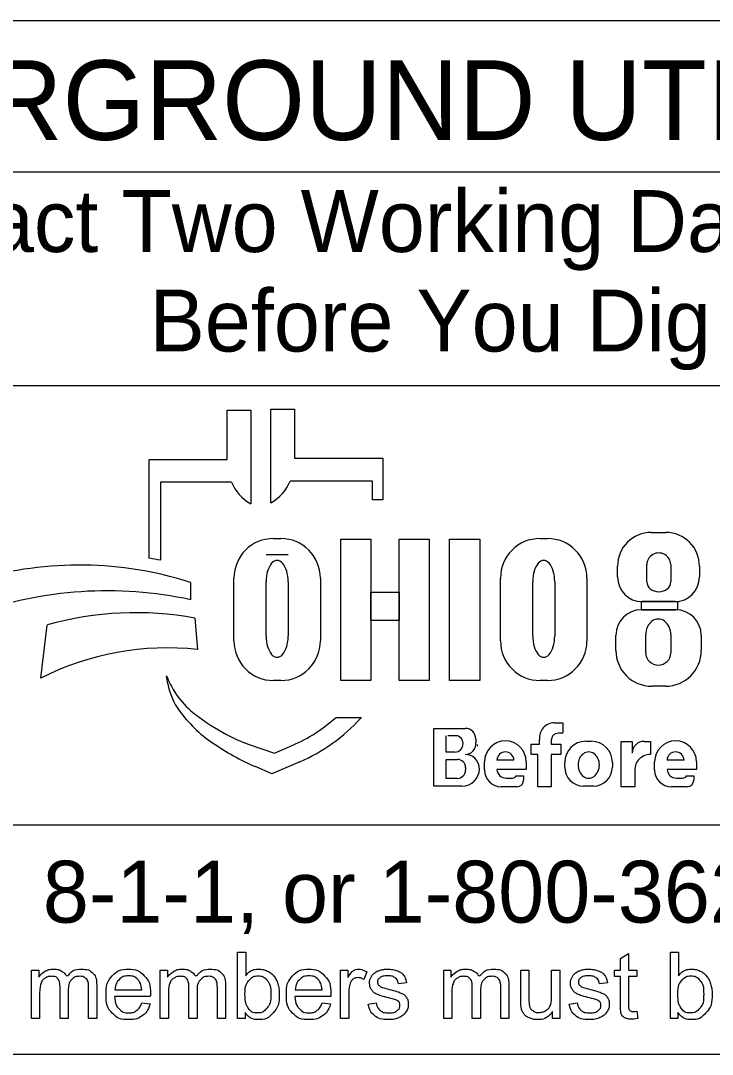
# Model space of a CAD drawing. Extents: x 0 to 59.1, y -2.4 to 22.
# Drawn here: x 4.266 to 5.83, y 2.633 to 4.97 of the extents above; entities that cross this region are included whole.
import ezdxf

# ---------------------------------------------------------------- set-up
doc = ezdxf.new("R2010")
doc.units = 0
doc.layers.add('SH_Data', color=7, linetype='Continuous')
doc.layers.add('SH_Text', color=7, linetype='Continuous')

msp = doc.modelspace()

# ---------------------------------------------------------------- linework, layer by layer
at = {"layer": 'SH_Data'}
for p, q in [((7.6263, 4.9702), (3.3763, 4.9702)), ((3.3763, 4.6287), (7.6263, 4.6287)), ((3.3763, 4.1453), (7.6263, 4.1453)), ((7.6263, 3.1506), (3.3763, 3.1506)), ((7.6263, 2.6327), (3.3763, 2.6327))]:
    msp.add_line(p, q, dxfattribs=at)
at = {"layer": 'SH_Text'}
for p, q in [((4.8317, 3.88), (4.8317, 4.092)), ((4.8317, 4.092), (4.8853, 4.092)), ((4.8853, 4.092), (4.8853, 3.9806)), ((4.7324, 3.9782), (4.7324, 4.0897)), ((4.7324, 4.0897), (4.786, 4.0897)), ((4.786, 4.0897), (4.786, 3.8777)), ((4.5564, 3.7543), (4.5564, 3.9782)), ((4.5564, 3.9782), (4.7324, 3.9782)), ((4.8853, 3.9806), (5.0846, 3.9806)), ((5.0846, 3.9806), (5.0846, 3.8867)), ((5.0613, 3.9291), (4.8749, 3.9291)), ((5.0613, 3.8867), (5.0613, 3.9291)), ((4.5817, 3.9268), (4.5817, 3.7499)), ((4.7428, 3.9268), (4.5817, 3.9268)), ((5.0846, 3.8867), (5.0613, 3.8867)), ((5.6919, 3.813), (5.7247, 3.813)), ((4.8374, 3.799), (4.8539, 3.799)), ((5.4404, 3.799), (5.4569, 3.799)), ((4.8706, 3.762), (4.8208, 3.762)), ((5.6818, 3.7011), (5.6818, 3.7403)), ((5.7359, 3.7403), (5.7359, 3.7011)), ((5.6156, 3.7124), (5.6156, 3.7367)), ((5.801, 3.7367), (5.801, 3.7124)), ((4.6497, 3.6997), (4.6497, 3.6608)), ((4.7479, 3.5676), (4.7479, 3.7096)), ((4.8208, 3.579), (4.8208, 3.7013)), ((4.8706, 3.7013), (4.8706, 3.579)), ((4.9434, 3.7096), (4.9434, 3.5676)), ((5.3509, 3.5676), (5.3509, 3.7096)), ((5.4238, 3.579), (5.4238, 3.7013)), ((5.4736, 3.7013), (5.4736, 3.579)), ((5.5464, 3.7096), (5.5464, 3.5676)), ((5.745, 3.6564), (5.6716, 3.6564)), ((5.6698, 3.6381), (5.7471, 3.6381)), ((4.3109, 3.4835), (4.3256, 3.6036)), ((4.6597, 3.6191), (4.6659, 3.5481)), ((5.6119, 3.5462), (5.6119, 3.5802)), ((5.6794, 3.5403), (5.6794, 3.5812)), ((5.7363, 3.5812), (5.7363, 3.5403)), ((5.805, 3.5802), (5.805, 3.5462)), ((4.5986, 3.4706), (4.5955, 3.4885)), ((4.8539, 3.4781), (4.8374, 3.4781)), ((5.4569, 3.4781), (5.4404, 3.4781)), ((5.7241, 3.4653), (5.6929, 3.4653)), ((4.9789, 3.3947), (5.0363, 3.3947)), ((5.2002, 3.239), (5.2002, 3.3697)), ((5.2002, 3.3697), (5.2713, 3.3697)), ((5.4727, 3.3825), (5.4922, 3.3825)), ((5.4922, 3.3825), (5.4922, 3.3595)), ((5.2281, 3.3162), (5.2281, 3.3532)), ((5.2533, 3.3532), (5.2321, 3.3532)), ((5.2951, 3.3459), (5.2951, 3.338)), ((5.4395, 3.3341), (5.4395, 3.3446)), ((5.4922, 3.359), (5.482, 3.359)), ((4.7804, 3.3344), (4.8399, 3.3139)), ((4.8399, 3.3139), (4.8809, 3.3317)), ((5.4201, 3.3111), (5.4201, 3.3341)), ((5.4201, 3.3341), (5.4395, 3.3341)), ((5.4656, 3.3425), (5.4656, 3.3341)), ((5.4656, 3.3341), (5.4871, 3.3341)), ((5.4871, 3.3341), (5.4871, 3.3111)), ((5.544, 3.3407), (5.5561, 3.3407)), ((5.6242, 3.2378), (5.6242, 3.3405)), ((5.6242, 3.3405), (5.6488, 3.3405)), ((5.6488, 3.3405), (5.6488, 3.3136)), ((5.676, 3.3405), (5.6899, 3.3405)), ((5.6899, 3.3405), (5.6899, 3.3108)), ((5.2475, 3.3162), (5.2281, 3.3162)), ((5.2281, 3.2568), (5.2281, 3.2997)), ((5.2281, 3.2997), (5.2537, 3.2997)), ((5.3813, 3.2981), (5.3428, 3.2981)), ((5.435, 3.3111), (5.4201, 3.3111)), ((5.435, 3.2378), (5.435, 3.3111)), ((5.4871, 3.3111), (5.4656, 3.3111)), ((5.4656, 3.3111), (5.4656, 3.2378)), ((5.7662, 3.2981), (5.7277, 3.2981)), ((4.8338, 3.2668), (4.7965, 3.2833)), ((4.8971, 3.2943), (4.8338, 3.2668)), ((5.2718, 3.2816), (5.2718, 3.2752)), ((5.3031, 3.2786), (5.3031, 3.2783)), ((5.3147, 3.2758), (5.3147, 3.2942)), ((5.4092, 3.2765), (5.3428, 3.2765)), ((5.4092, 3.2942), (5.4092, 3.2765)), ((5.4961, 3.2821), (5.4961, 3.2929)), ((5.6039, 3.2929), (5.6039, 3.2821)), ((5.6547, 3.2759), (5.6547, 3.2378)), ((5.6996, 3.2758), (5.6996, 3.2942)), ((5.7941, 3.2765), (5.7277, 3.2765)), ((5.7941, 3.2942), (5.7941, 3.2765)), ((5.2534, 3.2568), (5.2281, 3.2568)), ((5.3637, 3.2573), (5.3779, 3.2573)), ((5.3864, 3.2628), (5.4033, 3.2628)), ((5.4033, 3.2628), (5.4033, 3.253)), ((5.7487, 3.2573), (5.7628, 3.2573)), ((5.7713, 3.2628), (5.7882, 3.2628)), ((5.7882, 3.2628), (5.7882, 3.253)), ((5.2638, 3.239), (5.2002, 3.239)), ((5.3881, 3.2378), (5.3527, 3.2378)), ((5.4656, 3.2378), (5.435, 3.2378)), ((5.5611, 3.2393), (5.5389, 3.2393)), ((5.6547, 3.2378), (5.6242, 3.2378)), ((5.773, 3.2378), (5.7376, 3.2378))]:
    msp.add_line(p, q, dxfattribs=at)
for points in [[(4.9898, 3.798), (5.0578, 3.798), (5.0578, 3.478), (4.9898, 3.478)], [(5.1219, 3.798), (5.1899, 3.798), (5.1899, 3.478), (5.1219, 3.478)], [(5.2353, 3.798), (5.304, 3.798), (5.304, 3.478), (5.2353, 3.478)], [(5.0578, 3.6781), (5.1219, 3.6781), (5.1219, 3.6141), (5.0578, 3.6141)], [(5.6695, 3.6565), (5.7512, 3.6565), (5.7512, 3.638), (5.6695, 3.638)]]:
    msp.add_lwpolyline(points, close=True, dxfattribs=at)
for points in [[(4.7732, 2.7139), (4.7561, 2.7139), (4.7561, 2.864), (4.7745, 2.864), (4.7745, 2.8105)], [(5.6221, 2.7457), (5.6221, 2.8084), (5.6085, 2.8084), (5.6085, 2.8227), (5.6221, 2.8227), (5.6221, 2.8496), (5.6405, 2.8607), (5.6405, 2.8227), (5.659, 2.8227), (5.659, 2.8084), (5.6405, 2.8084), (5.6405, 2.7446)], [(5.7522, 2.7139), (5.7352, 2.7139), (5.7352, 2.864), (5.7536, 2.864), (5.7536, 2.8105)], [(4.2901, 2.7139), (4.2901, 2.8227), (4.3066, 2.8227), (4.3066, 2.8073)], [(4.5814, 2.7139), (4.5814, 2.8227), (4.5979, 2.8227), (4.5979, 2.8073)], [(4.9892, 2.7139), (4.9892, 2.8227), (5.0058, 2.8227), (5.0058, 2.8062)], [(5.0483, 2.8192), (5.0418, 2.8021)], [(5.2224, 2.7139), (5.2224, 2.8227), (5.2389, 2.8227), (5.2389, 2.8073)], [(5.3968, 2.7553), (5.3968, 2.8227), (5.4152, 2.8227), (5.4152, 2.7624)], [(5.4665, 2.7644), (5.4665, 2.8227), (5.4849, 2.8227), (5.4849, 2.7139), (5.4684, 2.7139)], [(4.3732, 2.777), (4.3732, 2.7139), (4.3547, 2.7139), (4.3547, 2.7845)], [(4.4376, 2.7885), (4.4376, 2.7139), (4.4192, 2.7139), (4.4192, 2.7824)], [(4.6645, 2.777), (4.6645, 2.7139), (4.6461, 2.7139), (4.6461, 2.7845)], [(4.729, 2.7885), (4.729, 2.7139), (4.7105, 2.7139), (4.7105, 2.7824)], [(5.1382, 2.7945), (5.1202, 2.7921)], [(5.3055, 2.777), (5.3055, 2.7139), (5.2871, 2.7139), (5.2871, 2.7845)], [(5.37, 2.7885), (5.37, 2.7139), (5.3515, 2.7139), (5.3515, 2.7824)], [(5.5928, 2.7945), (5.5747, 2.7921)], [(4.3085, 2.7703), (4.3085, 2.7139), (4.2901, 2.7139)], [(4.5588, 2.7635), (4.4777, 2.7635)], [(4.4787, 2.7786), (4.5395, 2.7786)], [(4.5999, 2.7703), (4.5999, 2.7139), (4.5814, 2.7139)], [(4.9668, 2.7635), (4.8857, 2.7635)], [(4.8867, 2.7786), (4.9475, 2.7786)], [(5.0077, 2.7708), (5.0077, 2.7139), (4.9892, 2.7139)], [(5.2409, 2.7703), (5.2409, 2.7139), (5.2224, 2.7139)], [(4.5393, 2.749), (4.5583, 2.7466)], [(4.9473, 2.749), (4.9663, 2.7466)], [(5.0518, 2.7464), (5.07, 2.7492)], [(5.5064, 2.7464), (5.5246, 2.7492)], [(4.7732, 2.7275), (4.7732, 2.7139)], [(5.4684, 2.7139), (5.4684, 2.7299)], [(5.659, 2.7303), (5.6616, 2.714)], [(5.7522, 2.7275), (5.7522, 2.7139)]]:
    msp.add_lwpolyline(points, dxfattribs=at)
for centre, radius, start, end in [((4.7836, 3.9659), 0.0985, 299.2531, 338.0704), ((4.8341, 3.9636), 0.0985, 201.9296, 240.7469), ((5.6919, 3.7367), 0.0763, 90, 180), ((5.7247, 3.7367), 0.0763, 0, 90), ((4.8374, 3.7096), 0.0895, 90, 180), ((4.8539, 3.7096), 0.0895, 0, 90), ((5.4404, 3.7096), 0.0895, 90, 180), ((5.4569, 3.7096), 0.0895, 0, 90), ((4.4283, 2.9454), 0.8191, 79.2074, 81.0007), ((4.3985, 2.9201), 0.8191, 72.1402, 106.3144), ((5.6716, 3.7124), 0.056, 180, 270), ((5.745, 3.7124), 0.056, 270, 0), ((4.4616, 2.789), 0.8919, 77.8238, 109.8274), ((4.5255, 2.8993), 0.7322, 79.44, 105.8467), ((5.6698, 3.5802), 0.0579, 90, 180), ((5.7471, 3.5802), 0.0579, 0, 90), ((4.8374, 3.5676), 0.0895, 180, 270), ((4.8539, 3.5676), 0.0895, 270, 0), ((5.4404, 3.5676), 0.0895, 180, 270), ((5.4569, 3.5676), 0.0895, 270, 0), ((4.5975, 2.9161), 0.6357, 83.8248, 116.8021), ((5.6929, 3.5462), 0.081, 180, 270), ((5.7241, 3.5462), 0.081, 270, 0), ((4.7829, 3.5606), 0.2008, 201.0457, 232.5314), ((4.7399, 3.4947), 0.1433, 189.6817, 216.0884), ((4.8735, 3.5921), 0.3088, 216.0884, 235.7167), ((4.9754, 3.8119), 0.5173, 232.5314, 241.794), ((4.7375, 3.6621), 0.3602, 293.4582, 312.0712), ((4.7375, 3.6621), 0.401, 293.4582, 317.8286), ((5.2713, 3.3459), 0.0238, 0, 90), ((5.4727, 3.349), 0.0335, 90, 187.5187), ((4.8903, 3.653), 0.3371, 241.794, 250.9821), ((5.2494, 3.3363), 0.0169, 357.8325, 90), ((5.482, 3.3425), 0.0165, 90, 180), ((5.0401, 3.8364), 0.6044, 235.7167, 246.2325), ((5.2475, 3.335), 0.0187, 270, 2.0582), ((5.2709, 3.3352), 0.0243, 270, 6.6529), ((5.2815, 3.3337), 0.0175, 347.4023, 0), ((5.362, 3.2942), 0.0473, 0, 180), ((5.544, 3.2929), 0.0478, 90, 180), ((5.5561, 3.2929), 0.0478, 0, 90), ((5.6756, 3.3136), 0.0269, 89.2449, 180), ((5.7469, 3.2942), 0.0473, 0, 180), ((5.2537, 3.2816), 0.0181, 0, 90), ((5.271, 3.2788), 0.0321, 4.0748, 90), ((5.362, 3.2972), 0.0193, 2.9632, 177.0368), ((5.6896, 3.2759), 0.0349, 89.6033, 180), ((5.7469, 3.2972), 0.0193, 2.9632, 177.0368), ((5.2534, 3.2752), 0.0184, 270, 0), ((5.2638, 3.2783), 0.0393, 270, 0), ((5.2702, 3.2786), 0.033, 0, 11.7502), ((5.3527, 3.2758), 0.038, 180, 270), ((5.3637, 3.2783), 0.021, 184.827, 270), ((5.5389, 3.2821), 0.0428, 180, 270), ((5.5611, 3.2821), 0.0428, 270, 0), ((5.7376, 3.2758), 0.038, 180, 270), ((5.7487, 3.2783), 0.021, 184.827, 270), ((5.3779, 3.2666), 0.00938, 270, 335.9979), ((5.3881, 3.253), 0.0152, 270, 0), ((5.7628, 3.2666), 0.00938, 270, 335.9979), ((5.773, 3.253), 0.0152, 270, 0)]:
    msp.add_arc(centre, radius, start, end, dxfattribs=at)
for centre, major_axis, ratio, start_param, end_param in [((5.7089, 3.7403), (0.0271, 0), 0.969373, 0, 3.141593), ((4.8457, 3.7013), (0, 0.0484), 0.514403, 4.712389, 7.853982), ((5.4487, 3.7013), (0, 0.0484), 0.514403, 4.712389, 7.853982), ((5.7089, 3.7011), (0.0271, 0), 0.818453, 3.141593, 6.283185), ((5.7078, 3.5812), (0, 0.0358), 0.794529, 4.712389, 7.853982), ((4.8457, 3.579), (0, 0.0484), 0.514403, 1.570796, 4.712389), ((5.4487, 3.579), (0, 0.0484), 0.514403, 1.570796, 4.712389), ((5.7078, 3.5403), (0.0284, 0), 0.959837, 3.141593, 6.283185), ((5.5505, 3.2875), (0, 0.029), 0.832186, 4.712389, 7.853982), ((5.5505, 3.2875), (0, 0.0302), 0.797287, 1.570796, 4.712389)]:
    msp.add_ellipse(centre, major_axis=major_axis, ratio=ratio, start_param=start_param, end_param=end_param, dxfattribs=at)
for points in [[(4.3066, 2.8073), (4.3117, 2.8153), (4.3202, 2.8202), (4.3287, 2.8251), (4.3396, 2.8251), (4.3516, 2.8251), (4.3594, 2.8201), (4.3671, 2.815), (4.3703, 2.806), (4.3832, 2.8251), (4.4039, 2.8251), (4.4202, 2.8251), (4.4289, 2.8161), (4.4376, 2.8072), (4.4376, 2.7885)], [(4.3547, 2.7845), (4.3547, 2.7968), (4.3502, 2.8029), (4.3457, 2.8091), (4.3355, 2.8091), (4.3277, 2.8091), (4.3211, 2.805), (4.3144, 2.8009), (4.3115, 2.793), (4.3085, 2.7851), (4.3085, 2.7703)], [(4.4192, 2.7824), (4.4192, 2.7934), (4.4174, 2.7983), (4.4156, 2.8031), (4.4109, 2.8061), (4.4062, 2.8091), (4.3998, 2.8091), (4.3883, 2.8091), (4.3807, 2.8014), (4.3732, 2.7938), (4.3732, 2.777)], [(4.5583, 2.7466), (4.5538, 2.7299), (4.5416, 2.7207), (4.5294, 2.7115), (4.5105, 2.7115), (4.4866, 2.7115), (4.4726, 2.7261), (4.4587, 2.7408), (4.4587, 2.7674), (4.4587, 2.7948), (4.4728, 2.8099), (4.4869, 2.8251), (4.5095, 2.8251), (4.5313, 2.8251), (4.5451, 2.8102), (4.5589, 2.7954), (4.5589, 2.7684), (4.5589, 2.7668), (4.5588, 2.7635)], [(4.5395, 2.7786), (4.5382, 2.7924), (4.5325, 2.7993), (4.5237, 2.81), (4.5096, 2.81), (4.4969, 2.81), (4.4883, 2.8015), (4.4796, 2.7929), (4.4787, 2.7786)], [(4.5979, 2.8073), (4.6031, 2.8153), (4.6116, 2.8202), (4.6201, 2.8251), (4.6309, 2.8251), (4.643, 2.8251), (4.6508, 2.8201), (4.6585, 2.815), (4.6617, 2.806), (4.6746, 2.8251), (4.6953, 2.8251), (4.7115, 2.8251), (4.7202, 2.8161), (4.729, 2.8072), (4.729, 2.7885)], [(4.6461, 2.7845), (4.6461, 2.7968), (4.6416, 2.8029), (4.6371, 2.8091), (4.6268, 2.8091), (4.619, 2.8091), (4.6124, 2.805), (4.6058, 2.8009), (4.6028, 2.793), (4.5999, 2.7851), (4.5999, 2.7703)], [(4.7105, 2.7824), (4.7105, 2.7934), (4.7087, 2.7983), (4.707, 2.8031), (4.7022, 2.8061), (4.6975, 2.8091), (4.6912, 2.8091), (4.6797, 2.8091), (4.6721, 2.8014), (4.6645, 2.7938), (4.6645, 2.777)], [(4.7729, 2.7691), (4.7729, 2.7495), (4.7782, 2.7408), (4.7869, 2.7266), (4.8018, 2.7266), (4.8138, 2.7266), (4.8226, 2.7371), (4.8314, 2.7476), (4.8314, 2.7684), (4.8314, 2.7897), (4.823, 2.7998), (4.8145, 2.81), (4.8026, 2.81), (4.7905, 2.81), (4.7817, 2.7995), (4.7729, 2.789), (4.7729, 2.7691)], [(4.7745, 2.8105), (4.7862, 2.8251), (4.8043, 2.8251), (4.8144, 2.8251), (4.8233, 2.8211), (4.8323, 2.817), (4.8381, 2.8097), (4.8439, 2.8024), (4.8471, 2.792), (4.8504, 2.7817), (4.8504, 2.7699), (4.8504, 2.742), (4.8366, 2.7267), (4.8228, 2.7115), (4.8034, 2.7115), (4.7841, 2.7115), (4.7732, 2.7275)], [(4.9663, 2.7466), (4.9618, 2.7299), (4.9496, 2.7207), (4.9374, 2.7115), (4.9185, 2.7115), (4.8946, 2.7115), (4.8806, 2.7261), (4.8667, 2.7408), (4.8667, 2.7674), (4.8667, 2.7948), (4.8808, 2.8099), (4.8949, 2.8251), (4.9175, 2.8251), (4.9393, 2.8251), (4.9531, 2.8102), (4.9669, 2.7954), (4.9669, 2.7684), (4.9669, 2.7668), (4.9668, 2.7635)], [(4.9475, 2.7786), (4.9462, 2.7924), (4.9405, 2.7993), (4.9317, 2.81), (4.9176, 2.81), (4.9049, 2.81), (4.8963, 2.8015), (4.8876, 2.7929), (4.8867, 2.7786)], [(5.0058, 2.8062), (5.0122, 2.8177), (5.0175, 2.8214), (5.0229, 2.8251), (5.0294, 2.8251), (5.0387, 2.8251), (5.0483, 2.8192)], [(5.0418, 2.8021), (5.0351, 2.8061), (5.0284, 2.8061), (5.0224, 2.8061), (5.0176, 2.8025), (5.0128, 2.7988), (5.0107, 2.7924), (5.0077, 2.7825), (5.0077, 2.7708)], [(5.1202, 2.7921), (5.1189, 2.8005), (5.113, 2.8053), (5.1071, 2.81), (5.0964, 2.81), (5.0836, 2.81), (5.0782, 2.8058), (5.0728, 2.8016), (5.0728, 2.7959), (5.0728, 2.7923), (5.075, 2.7895), (5.0773, 2.7865), (5.0821, 2.7845), (5.0849, 2.7835), (5.0984, 2.7798), (5.118, 2.7746), (5.1258, 2.7713), (5.1335, 2.768), (5.1379, 2.7616), (5.1424, 2.7553), (5.1424, 2.7458), (5.1424, 2.7366), (5.137, 2.7285), (5.1316, 2.7204), (5.1214, 2.7159), (5.1113, 2.7115), (5.0984, 2.7115), (5.0772, 2.7115), (5.066, 2.7203), (5.0549, 2.7291), (5.0518, 2.7464)], [(5.07, 2.7492), (5.0716, 2.7382), (5.0786, 2.7324), (5.0856, 2.7266), (5.0983, 2.7266), (5.111, 2.7266), (5.1172, 2.7317), (5.1234, 2.7369), (5.1234, 2.7439), (5.1234, 2.7502), (5.1179, 2.7537), (5.1141, 2.7562), (5.099, 2.76), (5.0787, 2.7651), (5.0709, 2.7689), (5.063, 2.7726), (5.059, 2.7792), (5.0549, 2.7858), (5.0549, 2.7938), (5.0549, 2.801), (5.0583, 2.8072), (5.0616, 2.8134), (5.0673, 2.8175), (5.0716, 2.8207), (5.0791, 2.8229), (5.0865, 2.8251), (5.095, 2.8251), (5.1079, 2.8251), (5.1176, 2.8214), (5.1273, 2.8177), (5.1319, 2.8114), (5.1365, 2.8051), (5.1382, 2.7945)], [(5.2389, 2.8073), (5.2441, 2.8153), (5.2526, 2.8202), (5.2611, 2.8251), (5.2719, 2.8251), (5.284, 2.8251), (5.2918, 2.8201), (5.2995, 2.815), (5.3027, 2.806), (5.3156, 2.8251), (5.3363, 2.8251), (5.3525, 2.8251), (5.3612, 2.8161), (5.37, 2.8072), (5.37, 2.7885)], [(5.2871, 2.7845), (5.2871, 2.7968), (5.2826, 2.8029), (5.2781, 2.8091), (5.2678, 2.8091), (5.26, 2.8091), (5.2534, 2.805), (5.2468, 2.8009), (5.2438, 2.793), (5.2409, 2.7851), (5.2409, 2.7703)], [(5.3515, 2.7824), (5.3515, 2.7934), (5.3497, 2.7983), (5.348, 2.8031), (5.3432, 2.8061), (5.3385, 2.8091), (5.3322, 2.8091), (5.3207, 2.8091), (5.3131, 2.8014), (5.3055, 2.7938), (5.3055, 2.777)], [(5.5747, 2.7921), (5.5735, 2.8005), (5.5676, 2.8053), (5.5617, 2.81), (5.5509, 2.81), (5.5382, 2.81), (5.5328, 2.8058), (5.5273, 2.8016), (5.5273, 2.7959), (5.5273, 2.7923), (5.5296, 2.7895), (5.5319, 2.7865), (5.5367, 2.7845), (5.5394, 2.7835), (5.553, 2.7798), (5.5726, 2.7746), (5.5803, 2.7713), (5.5881, 2.768), (5.5925, 2.7616), (5.5969, 2.7553), (5.5969, 2.7458), (5.5969, 2.7366), (5.5915, 2.7285), (5.5861, 2.7204), (5.576, 2.7159), (5.5658, 2.7115), (5.553, 2.7115), (5.5318, 2.7115), (5.5206, 2.7203), (5.5095, 2.7291), (5.5064, 2.7464)], [(5.5246, 2.7492), (5.5261, 2.7382), (5.5332, 2.7324), (5.5402, 2.7266), (5.5529, 2.7266), (5.5656, 2.7266), (5.5718, 2.7317), (5.5779, 2.7369), (5.5779, 2.7439), (5.5779, 2.7502), (5.5725, 2.7537), (5.5687, 2.7562), (5.5536, 2.76), (5.5333, 2.7651), (5.5254, 2.7689), (5.5176, 2.7726), (5.5135, 2.7792), (5.5095, 2.7858), (5.5095, 2.7938), (5.5095, 2.801), (5.5128, 2.8072), (5.5162, 2.8134), (5.5219, 2.8175), (5.5262, 2.8207), (5.5337, 2.8229), (5.5411, 2.8251), (5.5496, 2.8251), (5.5624, 2.8251), (5.5721, 2.8214), (5.5818, 2.8177), (5.5864, 2.8114), (5.5911, 2.8051), (5.5928, 2.7945)], [(5.752, 2.7691), (5.752, 2.7495), (5.7573, 2.7408), (5.766, 2.7266), (5.7808, 2.7266), (5.7929, 2.7266), (5.8017, 2.7371), (5.8105, 2.7476), (5.8105, 2.7684), (5.8105, 2.7897), (5.802, 2.7998), (5.7936, 2.81), (5.7816, 2.81), (5.7696, 2.81), (5.7608, 2.7995), (5.752, 2.789), (5.752, 2.7691)], [(5.7536, 2.8105), (5.7653, 2.8251), (5.7834, 2.8251), (5.7934, 2.8251), (5.8024, 2.8211), (5.8114, 2.817), (5.8171, 2.8097), (5.8229, 2.8024), (5.8262, 2.792), (5.8295, 2.7817), (5.8295, 2.7699), (5.8295, 2.742), (5.8156, 2.7267), (5.8018, 2.7115), (5.7825, 2.7115), (5.7632, 2.7115), (5.7522, 2.7275)], [(4.4777, 2.7635), (4.4787, 2.7456), (4.4878, 2.7361), (4.4969, 2.7266), (4.5106, 2.7266), (4.5207, 2.7266), (4.5279, 2.7319), (4.5351, 2.7373), (4.5393, 2.749)], [(4.8857, 2.7635), (4.8867, 2.7456), (4.8958, 2.7361), (4.9049, 2.7266), (4.9186, 2.7266), (4.9287, 2.7266), (4.9359, 2.7319), (4.9431, 2.7373), (4.9473, 2.749)], [(5.4152, 2.7624), (5.4152, 2.7479), (5.4163, 2.7429), (5.4181, 2.7357), (5.4237, 2.7315), (5.4293, 2.7274), (5.4376, 2.7274), (5.4459, 2.7274), (5.4532, 2.7316), (5.4604, 2.7359), (5.4634, 2.7432), (5.4665, 2.7505), (5.4665, 2.7644)], [(5.4684, 2.7299), (5.4557, 2.7115), (5.4339, 2.7115), (5.4243, 2.7115), (5.416, 2.7151), (5.4076, 2.7188), (5.4036, 2.7244), (5.3995, 2.73), (5.3979, 2.7381), (5.3968, 2.7435), (5.3968, 2.7553)], [(5.6616, 2.714), (5.6538, 2.7124), (5.6477, 2.7124), (5.6377, 2.7124), (5.6321, 2.7155), (5.6266, 2.7187), (5.6244, 2.7239), (5.6221, 2.7291), (5.6221, 2.7457)], [(5.6405, 2.7446), (5.6405, 2.7367), (5.6415, 2.7345), (5.6425, 2.7322), (5.6447, 2.7309), (5.6468, 2.7295), (5.6509, 2.7295), (5.654, 2.7295), (5.659, 2.7303)]]:
    msp.add_open_spline(points, degree=3, dxfattribs=at)

# ---------------------------------------------------------------- texts
for s, height, p in [('UNDERGROUND UTILITIES', 0.18, (3.5045, 4.7006)), ('Contact Two Working Days', 0.14, (3.796, 4.4471)), ('Before You Dig', 0.14, (4.5572, 4.2221)), ('OHIO811, 8-1-1, or 1-800-362-2764', 0.14, (3.4208, 2.9305))]:
    msp.add_text(s, height=height, dxfattribs=at).set_placement(p)

doc.saveas('drawing.dxf')
